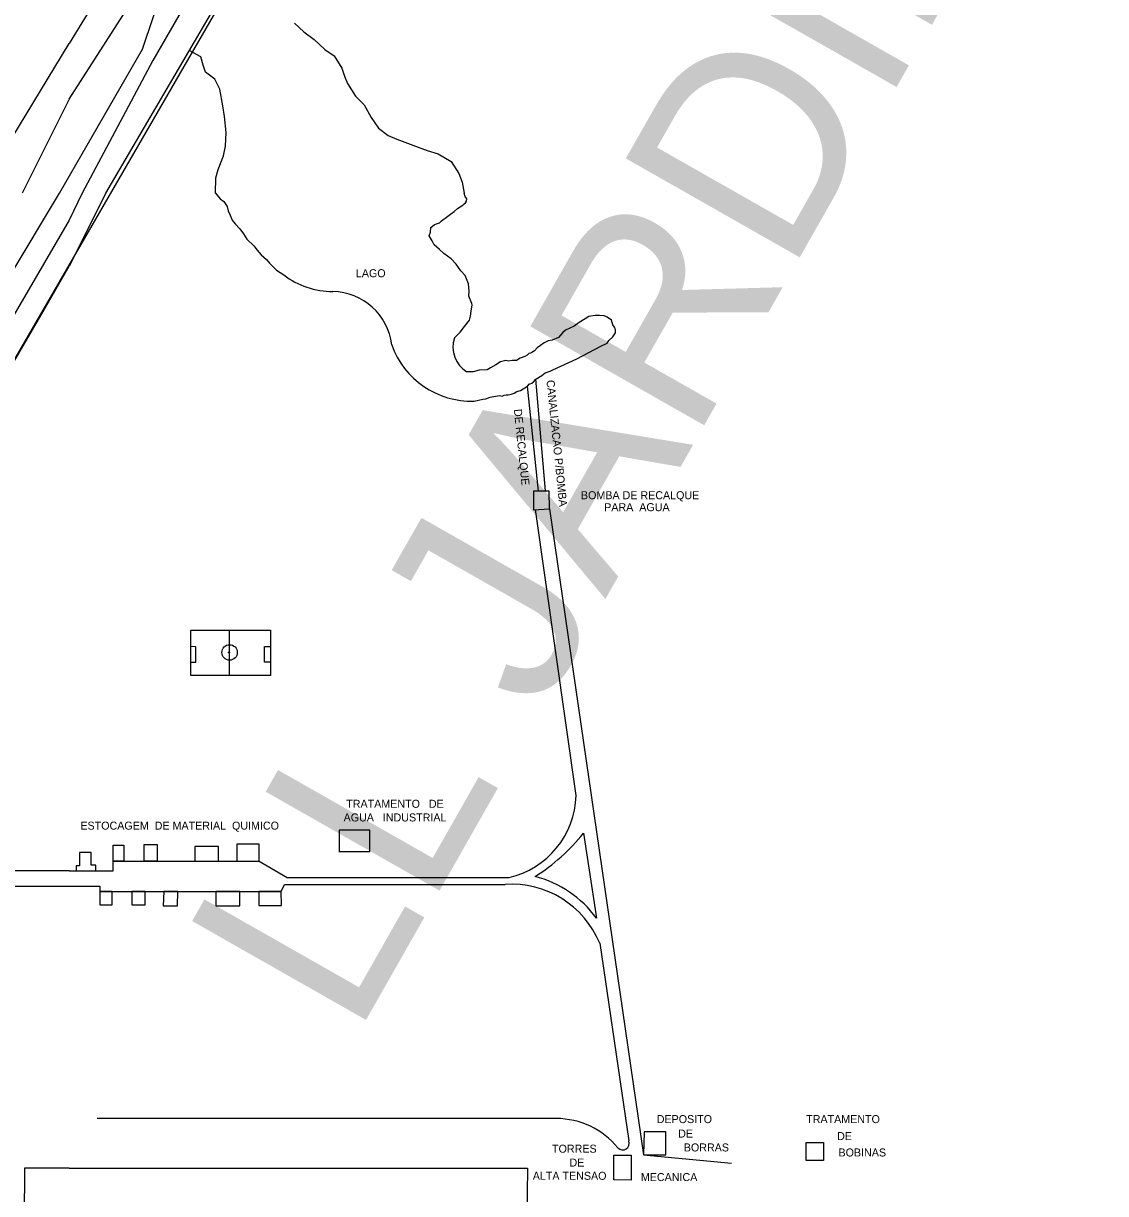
# Model space of a CAD drawing. Extents: x 325709 to 364434, y 7573432 to 7597073.
# Drawn here: x 339258 to 339799, y 7584002 to 7584587 of the extents above; entities that cross this region are included whole.
import ezdxf

# ---------------------------------------------------------------- set-up
doc = ezdxf.new("R2010")
doc.units = 0
for name, color, linetype in [('EDIFEXISTENT', 7, 'Continuous'), ('EDIFIDENTIF', 7, 'Continuous'), ('EDIFOBRAEXIS', 7, 'Continuous'), ('LIMITE_BAIRROS_MUNICIPIOS', 7, 'Continuous'), ('LOGRADOURO', 7, 'Continuous'), ('TUBO_PEAD_GN_125', 7, 'Continuous')]:
    doc.layers.add(name, color=color, linetype=linetype)

msp = doc.modelspace()

# ---------------------------------------------------------------- linework, layer by layer
at = {"layer": 'EDIFEXISTENT'}
for p, q in [((339521.32, 7584353), (339513.43, 7584353)), ((339513.43, 7584353), (339513.43, 7584343.74)), ((339521.47, 7584344.12), (339521.32, 7584353)), ((339513.43, 7584343.74), (339521.47, 7584344.12)), ((339431.58, 7584183.54), (339416.33, 7584183.54)), ((339416.33, 7584183.54), (339416.33, 7584172.93)), ((339431.58, 7584172.83), (339431.58, 7584183.54)), ((339292.37, 7584172.33), (339286.46, 7584172.33)), ((339286.46, 7584172.33), (339286.46, 7584165.76)), ((339292.37, 7584166.11), (339292.37, 7584172.33)), ((339303.34, 7584167.99), (339303.34, 7584176.04)), ((339303.34, 7584176.04), (339308.71, 7584176.04)), ((339308.71, 7584176.04), (339308.71, 7584167.99)), ((339318.78, 7584167.99), (339318.78, 7584176.32)), ((339318.78, 7584176.32), (339325.4, 7584176.32)), ((339325.4, 7584176.32), (339325.33, 7584167.99)), ((339356.03, 7584175.43), (339344.13, 7584175.43)), ((339344.13, 7584175.43), (339344.18, 7584167.99)), ((339356.03, 7584167.99), (339356.03, 7584175.43)), ((339376.27, 7584176.5), (339365.18, 7584176.5)), ((339365.18, 7584176.5), (339365.18, 7584167.99)), ((339376.27, 7584167.99), (339376.27, 7584176.5)), ((339416.21, 7584172.83), (339431.58, 7584172.83)), ((339294.73, 7584166.11), (339292.37, 7584166.11)), ((339294.73, 7584163.17), (339294.73, 7584166.11)), ((339308.71, 7584167.99), (339303.34, 7584167.99)), ((339325.33, 7584167.99), (339318.78, 7584167.99)), ((339344.18, 7584167.99), (339356.03, 7584167.99)), ((339365.18, 7584167.99), (339376.27, 7584167.99)), ((339286.46, 7584165.76), (339284.76, 7584165.76)), ((339284.76, 7584165.76), (339284.78, 7584163.17)), ((339284.78, 7584163.17), (339294.73, 7584163.17)), ((339296.71, 7584152.9), (339296.71, 7584146.3)), ((339302.85, 7584152.9), (339296.71, 7584152.9)), ((339302.77, 7584146.3), (339302.85, 7584152.9)), ((339312.64, 7584152.9), (339312.64, 7584146.23)), ((339319.39, 7584152.9), (339312.64, 7584152.9)), ((339319.37, 7584146.23), (339319.39, 7584152.9)), ((339328.6, 7584152.9), (339328.4, 7584145.72)), ((339335.6, 7584152.9), (339328.6, 7584152.9)), ((339335.48, 7584145.72), (339335.6, 7584152.9)), ((339354.71, 7584152.9), (339354.71, 7584145.75)), ((339366.63, 7584152.9), (339354.71, 7584152.9)), ((339366.66, 7584145.75), (339366.63, 7584152.9)), ((339376.07, 7584152.9), (339376.07, 7584145.93)), ((339387.31, 7584152.9), (339376.07, 7584152.9)), ((339387.41, 7584145.93), (339387.31, 7584152.9)), ((339296.71, 7584146.3), (339302.77, 7584146.3)), ((339312.64, 7584146.23), (339319.37, 7584146.23)), ((339328.4, 7584145.72), (339335.48, 7584145.72)), ((339354.71, 7584145.75), (339366.66, 7584145.75)), ((339376.07, 7584145.93), (339387.41, 7584145.93)), ((339568.71, 7584032.82), (339568.45, 7584021.28)), ((339579.52, 7584032.82), (339568.71, 7584032.82)), ((339579.52, 7584021.28), (339579.52, 7584032.82)), ((339649.67, 7584027.53), (339658.47, 7584027.53)), ((339649.8, 7584020.45), (339649.67, 7584027.53)), ((339658.47, 7584027.53), (339658.47, 7584018.5)), ((339553.66, 7584008.82), (339553.66, 7584021.05)), ((339553.66, 7584021.05), (339562.21, 7584021.05)), ((339562.21, 7584021.05), (339562.21, 7584008.64)), ((339568.45, 7584021.28), (339579.52, 7584021.28)), ((339649.8, 7584018.5), (339649.8, 7584020.45)), ((339259.08, 7584014.63), (339259.07, 7584001.91)), ((339281.39, 7584014.64), (339259.08, 7584014.63)), ((339281.39, 7584014.64), (339510.44, 7584014.64)), ((339510.44, 7584014.64), (339510.3, 7584001.91)), ((339658.47, 7584018.5), (339649.8, 7584018.5)), ((339562.21, 7584008.64), (339553.66, 7584008.82)), ((339259.04, 7583916.29), (339259.07, 7584001.91)), ((339510.3, 7584001.91), (339510.3, 7583996.15))]:
    msp.add_line(p, q, dxfattribs=at)
at = {"layer": 'EDIFOBRAEXIS'}
for p, q in [((339281.39, 7584548.99), (339257.88, 7584501.91)), ((339287.9, 7584501.89), (339281.39, 7584488.43)), ((339519.37, 7584353.11), (339514.54, 7584409)), ((339515.87, 7584352.93), (339510.48, 7584405.55)), ((339534.78, 7584200.87), (339514.44, 7584343.85)), ((339521.47, 7584344.12), (339568.45, 7584021.28)), ((339361.34, 7584283.57), (339361.24, 7584260.81)), ((339538.39, 7584182), (339544.95, 7584139.56)), ((339281.39, 7584163.17), (339166.74, 7584163.14)), ((339175.38, 7584155.45), (339281.38, 7584155.55)), ((339546.55, 7584127.02), (339561.1, 7584028.25)), ((339524.84, 7584039.46), (339295.3, 7584039.46)), ((339524.84, 7584039.46), (339524.84, 7584039.46)), ((339568.45, 7584021.28), (339612.48, 7584017.06))]:
    msp.add_line(p, q, dxfattribs=at)
for points in [[(339541.79, 7584943.58), (339447.41, 7584781.66), (339387.4, 7584679.71), (339323.12, 7584568.34), (339287.9, 7584501.89)], [(339276.52, 7584501.91), (339318.04, 7584574), (339328.89, 7584606.28), (339379.53, 7584689.38), (339424.14, 7584771.3), (339458.48, 7584828.92), (339491.79, 7584871.92), (339523.38, 7584928)], [(339281.39, 7584548.99), (339341.04, 7584642.15), (339400.22, 7584743.97), (339496.82, 7584900)], [(339394.05, 7584586.93), (339398.7, 7584582.54), (339403.86, 7584578.85), (339409.12, 7584573.85), (339413.77, 7584570.6), (339413.77, 7584570.6), (339417.62, 7584564.42), (339418.96, 7584560.43), (339420.46, 7584556.76), (339420.46, 7584556.76), (339424.43, 7584550.45), (339428.73, 7584546.18), (339432.25, 7584539.82), (339436.01, 7584534.45), (339440.76, 7584530.74), (339445.17, 7584528.96), (339453.07, 7584525.91), (339460.38, 7584523.25), (339465.83, 7584521.58), (339472.23, 7584517.81), (339476.1, 7584511.73), (339477.86, 7584507.44), (339477.86, 7584507.44), (339478.82, 7584501.91)], [(339354.47, 7584501.91), (339354.71, 7584509.56), (339355.75, 7584513.86), (339355.75, 7584513.86), (339358.41, 7584520.63), (339359.47, 7584525.37), (339359.74, 7584532.21), (339358.91, 7584540.31), (339358.11, 7584545.6), (339356.72, 7584553.9), (339354.1, 7584558.99), (339354.1, 7584558.99), (339349.55, 7584562.37), (339349.55, 7584562.37), (339348.29, 7584565.95), (339347.12, 7584570.04), (339347.12, 7584570.04), (339341.34, 7584573.25)], [(339185.7, 7584350.62), (339186.44, 7584351.88), (339218.4, 7584404.99), (339250.93, 7584459.19), (339276.52, 7584501.91)], [(339354.47, 7584501.91), (339356.82, 7584499.17), (339358.67, 7584497.78), (339360.37, 7584495.32), (339360.86, 7584493.21), (339361.8, 7584490.93), (339362.86, 7584488.47), (339364.31, 7584486.67), (339366.62, 7584484.08), (339368.44, 7584481.59), (339370.14, 7584478.93), (339373.62, 7584475.68), (339375.29, 7584473.53), (339377.27, 7584471.09), (339380.01, 7584468.73), (339381.56, 7584466.93), (339384.96, 7584463.51), (339388.59, 7584461.07)], [(339473.89, 7584429.65), (339476.71, 7584432.51), (339478.99, 7584435.38), (339481.43, 7584438.5), (339481.88, 7584440.56), (339482.32, 7584443.02), (339482.75, 7584446.14), (339482.59, 7584446.87), (339481.05, 7584450.55), (339481.27, 7584452.91), (339480.94, 7584456.72), (339479.29, 7584460.78), (339477.11, 7584463.19), (339474.73, 7584466.49), (339472.32, 7584469.2), (339468.64, 7584471.86), (339466.53, 7584473.72), (339463.84, 7584476.15), (339462.75, 7584478.08), (339461.35, 7584480.64), (339461.89, 7584482.47), (339462.06, 7584484.73), (339463.94, 7584486.27), (339466.5, 7584487.16), (339467.52, 7584488.18), (339468.18, 7584488.68), (339469.93, 7584489.93), (339471.25, 7584490.99), (339473.81, 7584492.77), (339475.46, 7584494.27), (339478.12, 7584495.92), (339478.86, 7584496.55), (339479.47, 7584497.19), (339479.9, 7584497.97), (339480.05, 7584499.11), (339479.29, 7584500.31), (339478.82, 7584501.91)], [(339281.39, 7584488.43), (339166.72, 7584292.05), (339166.72, 7584292.05), (339166.72, 7584292.05), (339166.72, 7584292.05), (339166.72, 7584292.05), (339166.72, 7584292.05), (339166.72, 7584292.05), (339093.22, 7584162.66), (339043.04, 7584074.5)], [(339483.77, 7584398.06), (339488.06, 7584398.95), (339489.63, 7584399.15), (339491.81, 7584399.94), (339494.45, 7584400.55), (339496.53, 7584400.75), (339497.75, 7584400.45), (339498.71, 7584400.93), (339499.78, 7584401.11), (339500.72, 7584401.23), (339501.55, 7584401.31), (339502.36, 7584401.51), (339503.86, 7584401.97), (339505.13, 7584402.86), (339506.93, 7584403.37), (339510.48, 7584405.55), (339511.4, 7584406.59), (339511.75, 7584406.59), (339512.64, 7584407.07), (339513.48, 7584407.58), (339514.54, 7584409), (339517.56, 7584410.85), (339519.24, 7584412.15), (339521.8, 7584413.03), (339523.17, 7584413.64), (339535.17, 7584419.12), (339547.17, 7584425.42), (339550.24, 7584426.92), (339551.07, 7584428.31), (339553.08, 7584430.16), (339554.47, 7584432.14), (339554.45, 7584433.66), (339554.02, 7584435.06), (339553.13, 7584436.1), (339552.39, 7584438.48), (339550.24, 7584440.01), (339549.96, 7584440.16), (339548.71, 7584440.62), (339546.4, 7584440.87), (339544.32, 7584440.87), (339541.18, 7584440.36), (339539.3, 7584439.17), (339536.26, 7584437.24), (339533.72, 7584435.56), (339529.38, 7584433.51), (339528.04, 7584432.27), (339525.91, 7584429.88), (339522.76, 7584428.48), (339520.73, 7584428.13), (339518.75, 7584427.11), (339516.87, 7584425.87), (339515.3, 7584424.6), (339514.01, 7584423.08), (339512.59, 7584422.27), (339511.88, 7584421.99), (339511.04, 7584421.76), (339510.23, 7584421), (339509.06, 7584420.34), (339506.75, 7584419.53), (339505, 7584418.36), (339502.72, 7584418.26), (339500.92, 7584417.93), (339499.6, 7584418.26), (339496.93, 7584417.72), (339494.6, 7584416.2), (339491.96, 7584414.58), (339490.26, 7584413.64), (339486.25, 7584413.51), (339483.21, 7584412.72), (339480.19, 7584412.65)], [(339342.08, 7584283.57), (339382.02, 7584283.57), (339382.02, 7584260.81), (339342.11, 7584260.81), (339342.08, 7584283.57)], [(339342.1, 7584267.56), (339344.65, 7584267.56), (339344.65, 7584275.27), (339342.09, 7584275.32)], [(339382.02, 7584267.59), (339378.95, 7584267.59), (339378.95, 7584275.35), (339382.02, 7584275.3)], [(339281.39, 7584163.17), (339303.34, 7584163.17), (339303.34, 7584167.99), (339376.27, 7584167.99), (339390.34, 7584159.83), (339501.2, 7584159.87)], [(339281.38, 7584155.55), (339296.71, 7584155.55), (339296.71, 7584152.9), (339387.31, 7584152.9), (339389.01, 7584156.49), (339499.22, 7584156.49)]]:
    msp.add_lwpolyline(points, dxfattribs=at)
for centre, radius in [((339361.54, 7584272.4), 3.86), ((339361.24, 7584272.38), 0.254)]:
    msp.add_circle(centre, radius, dxfattribs=at)
for centre, radius, start, end in [((339413.55, 7584494.46), 41.69, 233.22727, 269.492), ((339412.62, 7584422.64), 30.14, 6.67353, 88.94141), ((339487.8, 7584425.13), 14.62, 162.00848, 238.62989), ((339482.33, 7584440.22), 42.19, 199.4977, 271.95606), ((339491.2, 7584202.32), 43.61, 283.2644, 358.09478), ((339463.1, 7584241.97), 96.25, 302.0766, 321.46554), ((339500.37, 7584106.93), 55.24, 36.19798, 75.48081), ((339502.34, 7584108.75), 47.83, 22.45349, 93.73391), ((339524.48, 7583999.07), 40.4, 39.52635, 89.49174), ((339558.05, 7584027.02), 3.29, 222.91658, 22.10913)]:
    msp.add_arc(centre, radius, start, end, dxfattribs=at)
at = {"layer": 'LOGRADOURO'}
for p, q in [((339319.3, 7584639.62), (339281.39, 7584576.81)), ((339235.93, 7584501.91), (339281.39, 7584576.81)), ((339299.62, 7584501.91), (339281.39, 7584465.49))]:
    msp.add_line(p, q, dxfattribs=at)
for points in [[(339299.62, 7584501.91), (339395.07, 7584665.14), (339487.05, 7584819.37), (339490.05, 7584841.87), (339544.58, 7584935.74)], [(339034.46, 7584031.52), (339087.39, 7584125.24), (339174.05, 7584280.6), (339174.05, 7584280.6), (339174.05, 7584280.6), (339215.6, 7584352.31), (339268.29, 7584442.79), (339281.39, 7584465.49)]]:
    msp.add_lwpolyline(points, dxfattribs=at)
at = {"layer": 'TUBO_PEAD_GN_125'}
msp.add_lwpolyline([(339053.68, 7584072.86), (339441.06, 7584742.26), (339490.05, 7584841.87), (339544.58, 7584935.74), (339561.88, 7585005.03)], dxfattribs=at)

# ---------------------------------------------------------------- texts
at = {"layer": 'EDIFIDENTIF'}
for s, p in [('LAGO', (339424.66, 7584459.94)), ('BOMBA DE RECALQUE', (339537.17, 7584348.98)), ('PARA  AGUA', (339548.78, 7584343.01)), ('TRATAMENTO   DE', (339419.85, 7584194.75)), ('AGUA   INDUSTRIAL', (339418.52, 7584187.93)), ('ESTOCAGEM  DE MATERIAL  QUIMICO', (339286.95, 7584183.83)), ('DEPOSITO', (339575.06, 7584037.15)), ('TRATAMENTO', (339649.76, 7584037.15)), ('DE ', (339585.75, 7584029.91)), ('DE ', (339665.2, 7584028.65)), ('TORRES', (339522.72, 7584022.35)), ('BORRAS', (339588.58, 7584022.98)), ('BOBINAS', (339665.91, 7584020.46)), ('DE', (339531.44, 7584015.42)), ('ALTA TENSAO', (339513.08, 7584008.81)), ('MECANICA', (339567.12, 7584008.18))]:
    msp.add_text(s, height=4, dxfattribs=at).set_placement(p)
for s, p in [('CANALIZACAO P/BOMBA', (339519.92, 7584408.39)), ('DE RECALQUE', (339503.63, 7584393.88))]:
    msp.add_text(s, height=4, rotation=275.84366, dxfattribs=at).set_placement(p)
at = {"layer": 'LIMITE_BAIRROS_MUNICIPIOS'}
msp.add_text('LL JARDIM PARAISO - CENTRO', height=100, rotation=60.3713, dxfattribs=at).set_placement((339424.31, 7584079.17))

doc.saveas('drawing.dxf')
